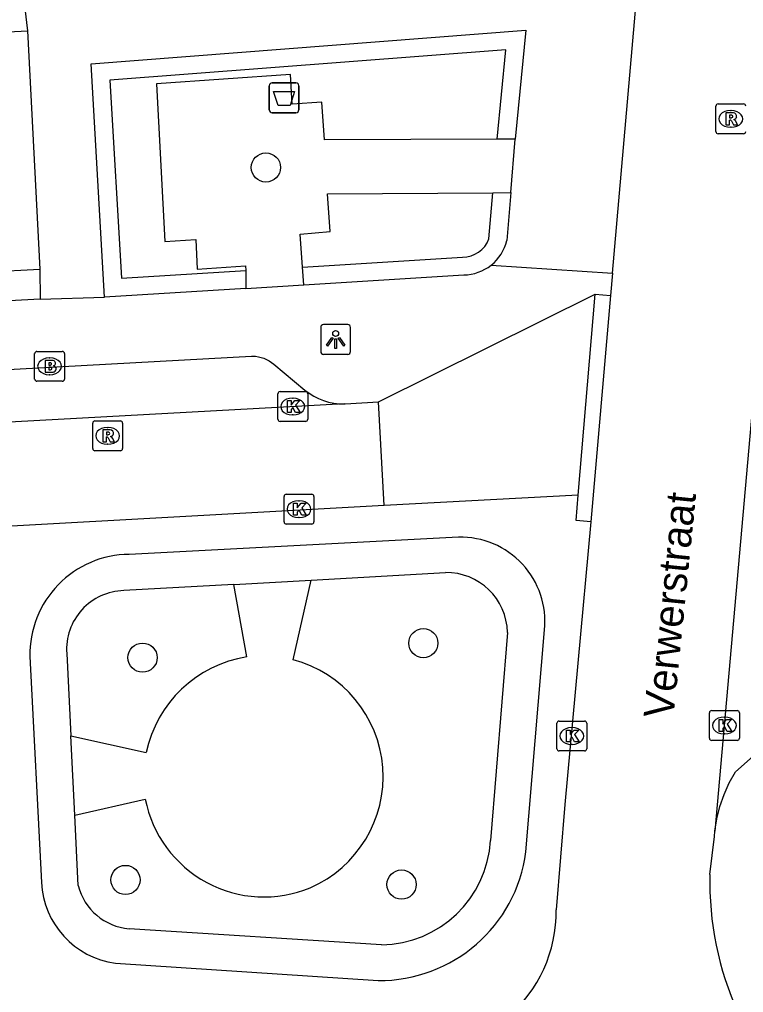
# Model space of a CAD drawing. Extents: x 160861 to 161308, y 384024 to 384878.
# Drawn here: x 161108.92 to 161133.18, y 384701.45 to 384734.04 of the extents above; entities that cross this region are included whole.
import ezdxf

# ---------------------------------------------------------------- set-up
doc = ezdxf.new("R2010")
doc.units = 0
for name, color, linetype in [('IMGEO_Afvalbak', 7, 'Continuous'), ('IMGEO_Boom', 7, 'Continuous'), ('IMGEO_Brandkraan', 7, 'Continuous'), ('IMGEO_Haag', 7, 'Continuous'), ('IMGEO_Kolk', 7, 'Continuous'), ('IMGEO_Lichtpunt', 7, 'Continuous'), ('IMGEO_Openbare_ruimte_label', 7, 'Continuous'), ('IMGEO_Pand', 7, 'Continuous'), ('IMGEO_Rijbaan_lokaal_open', 7, 'Continuous'), ('IMGEO_Rioolput', 7, 'Continuous'), ('IMGEO_Voetpad_open', 7, 'Continuous')]:
    doc.layers.add(name, color=color, linetype=linetype)

msp = doc.modelspace()

# ---------------------------------------------------------------- linework, layer by layer
at = {"layer": 'IMGEO_Afvalbak'}
for p, q in [((161117.289, 384731.014), (161117.289, 384731.814)), ((161117.289, 384731.814), (161117.289, 384731.014)), ((161117.389, 384731.914), (161118.179, 384731.914)), ((161118.179, 384731.914), (161117.389, 384731.914)), ((161118.279, 384731.814), (161118.279, 384731.014)), ((161118.279, 384731.014), (161118.279, 384731.814)), ((161118.179, 384730.914), (161117.389, 384730.914)), ((161117.389, 384730.914), (161118.179, 384730.914))]:
    msp.add_line(p, q, dxfattribs=at)
msp.add_lwpolyline([(161117.432, 384731.628), (161118.136, 384731.628), (161117.987, 384731.158), (161117.581, 384731.158), (161117.432, 384731.628)], dxfattribs=at)
for centre, start, end in [((161117.389, 384731.814), 90, 180), ((161117.389, 384731.814), 90, 180), ((161118.179, 384731.814), 0, 90), ((161118.179, 384731.814), 360, 90), ((161117.389, 384731.014), 180, 270), ((161117.389, 384731.014), 180, 270), ((161118.179, 384731.014), 270, 0), ((161118.179, 384731.014), 270, 0)]:
    msp.add_arc(centre, 0.1, start, end, dxfattribs=at)
at = {"layer": 'IMGEO_Boom'}
for centre in [(161117.175, 384729.078), (161122.448, 384713.149), (161113.042, 384712.663), (161112.47, 384705.218), (161121.719, 384705.064)]:
    msp.add_circle(centre, 0.489, dxfattribs=at)
at = {"layer": 'IMGEO_Brandkraan'}
for p, q in [((161109.427, 384721.993), (161109.427, 384722.845)), ((161109.502, 384722.919), (161110.354, 384722.919)), ((161110.428, 384722.845), (161110.428, 384721.993)), ((161109.915, 384722.699), (161109.94, 384722.699)), ((161110.354, 384721.919), (161109.502, 384721.919)), ((161109.938, 384722.139), (161109.913, 384722.139))]:
    msp.add_line(p, q, dxfattribs=at)
for points in [[(161109.427, 384721.993), (161109.427, 384722.845)], [(161109.502, 384722.919), (161110.354, 384722.919)], [(161110.428, 384722.845), (161110.428, 384721.993)], [(161109.775, 384722.619), (161109.775, 384722.219), (161109.988, 384722.219)], [(161110.006, 384722.619), (161109.775, 384722.619)], [(161109.954, 384722.538), (161109.9, 384722.538), (161109.9, 384722.462)], [(161109.9, 384722.462), (161109.953, 384722.462)], [(161109.962, 384722.386), (161109.9, 384722.386), (161109.9, 384722.305)], [(161109.9, 384722.305), (161109.962, 384722.305)], [(161110.354, 384721.919), (161109.502, 384721.919)]]:
    msp.add_lwpolyline(points, dxfattribs=at)
for centre, radius, start, end in [((161109.504, 384722.843), 0.0765, 91.552, 178.448), ((161109.504, 384722.843), 0.0765, 91.552, 178.448), ((161110.352, 384722.843), 0.0765, 1.552, 88.448), ((161110.352, 384722.843), 0.0765, 1.552, 88.448), ((161109.955, 384722.5), 0.0379, 267.8285, 90.9355), ((161110.01, 384722.474), 0.145, 59.4692, 91.5367), ((161110.035, 384722.521), 0.0922, 285.5137, 58.1501), ((161109.963, 384722.345), 0.0404, 269.8759, 90.5077), ((161109.994, 384722.47), 0.251, 268.6676, 293.5347), ((161110.04, 384722.329), 0.105, 301.3115, 78.989), ((161109.504, 384721.995), 0.0765, 181.552, 268.448), ((161109.504, 384721.995), 0.0765, 181.552, 268.448), ((161110.352, 384721.995), 0.0765, 271.552, 358.448), ((161110.352, 384721.995), 0.0765, 271.552, 358.448)]:
    msp.add_arc(centre, radius, start, end, dxfattribs=at)
for centre, major_axis, ratio, start_param, end_param in [((161109.914, 384722.419), (-0.387, 0.002), 0.722429, 4.712389, 7.853982), ((161109.939, 384722.419), (-0.39, 0.002), 0.717154, 1.570796, 4.712389)]:
    msp.add_ellipse(centre, major_axis=major_axis, ratio=ratio, start_param=start_param, end_param=end_param, dxfattribs=at)
at = {"layer": 'IMGEO_Haag'}
for points in [[(161124.926, 384730.028), (161125.216, 384733.021), (161111.949, 384732), (161112.335, 384725.367), (161116.498, 384725.626)], [(161124.646, 384726.684), (161124.777, 384728.232)], [(161118.403, 384725.745), (161123.764, 384726.079)]]:
    msp.add_lwpolyline(points, dxfattribs=at)
msp.add_arc((161123.771, 384727.014), 0.935, 269.5774, 339.3182, dxfattribs=at)
at = {"layer": 'IMGEO_Kolk'}
for p, q in [((161117.648, 384721.572), (161118.5, 384721.572)), ((161117.573, 384720.646), (161117.573, 384721.498)), ((161118.061, 384721.352), (161118.086, 384721.352)), ((161118.574, 384721.498), (161118.574, 384720.646)), ((161118.5, 384720.572), (161117.648, 384720.572)), ((161118.084, 384720.792), (161118.059, 384720.792)), ((161117.783, 384717.209), (161117.783, 384718.061)), ((161117.858, 384718.135), (161118.71, 384718.135)), ((161118.784, 384718.061), (161118.784, 384717.209)), ((161118.271, 384717.915), (161118.296, 384717.915)), ((161118.294, 384717.355), (161118.269, 384717.355)), ((161118.71, 384717.135), (161117.858, 384717.135)), ((161132.034, 384709.965), (161132.034, 384710.817)), ((161132.109, 384710.891), (161132.961, 384710.891)), ((161133.035, 384710.817), (161133.035, 384709.965)), ((161126.923, 384709.613), (161126.923, 384710.465)), ((161126.998, 384710.539), (161127.85, 384710.539)), ((161127.924, 384710.465), (161127.924, 384709.613)), ((161132.522, 384710.671), (161132.547, 384710.671)), ((161127.411, 384710.319), (161127.436, 384710.319)), ((161132.961, 384709.891), (161132.109, 384709.891)), ((161132.545, 384710.111), (161132.52, 384710.111)), ((161127.85, 384709.539), (161126.998, 384709.539)), ((161127.434, 384709.759), (161127.409, 384709.759))]:
    msp.add_line(p, q, dxfattribs=at)
for points in [[(161117.648, 384721.572), (161118.5, 384721.572)], [(161117.573, 384720.646), (161117.573, 384721.498)], [(161117.894, 384721.272), (161118.017, 384721.272), (161118.017, 384721.121), (161118.147, 384721.272), (161118.311, 384721.272), (161118.165, 384721.121), (161118.318, 384720.872), (161118.166, 384720.872), (161118.081, 384721.036), (161118.017, 384720.969), (161118.017, 384720.872), (161117.894, 384720.872), (161117.894, 384721.272)], [(161118.574, 384721.498), (161118.574, 384720.646)], [(161118.5, 384720.572), (161117.648, 384720.572)], [(161117.783, 384717.209), (161117.783, 384718.061)], [(161117.858, 384718.135), (161118.71, 384718.135)], [(161118.784, 384718.061), (161118.784, 384717.209)], [(161118.104, 384717.835), (161118.227, 384717.835), (161118.227, 384717.684), (161118.357, 384717.835), (161118.521, 384717.835), (161118.375, 384717.684), (161118.528, 384717.435), (161118.376, 384717.435), (161118.291, 384717.599), (161118.227, 384717.532), (161118.227, 384717.435), (161118.104, 384717.435), (161118.104, 384717.835)], [(161118.71, 384717.135), (161117.858, 384717.135)], [(161132.034, 384709.965), (161132.034, 384710.817)], [(161132.109, 384710.891), (161132.961, 384710.891)], [(161133.035, 384710.817), (161133.035, 384709.965)], [(161126.923, 384709.613), (161126.923, 384710.465)], [(161126.998, 384710.539), (161127.85, 384710.539)], [(161127.924, 384710.465), (161127.924, 384709.613)], [(161132.355, 384710.591), (161132.478, 384710.591), (161132.478, 384710.44), (161132.608, 384710.591), (161132.772, 384710.591), (161132.626, 384710.44), (161132.779, 384710.191), (161132.627, 384710.191), (161132.542, 384710.355), (161132.478, 384710.288), (161132.478, 384710.191), (161132.355, 384710.191), (161132.355, 384710.591)], [(161127.244, 384710.239), (161127.367, 384710.239), (161127.367, 384710.088), (161127.497, 384710.239), (161127.661, 384710.239), (161127.515, 384710.088), (161127.668, 384709.839), (161127.516, 384709.839), (161127.431, 384710.003), (161127.367, 384709.936), (161127.367, 384709.839), (161127.244, 384709.839), (161127.244, 384710.239)], [(161132.961, 384709.891), (161132.109, 384709.891)], [(161127.85, 384709.539), (161126.998, 384709.539)]]:
    msp.add_lwpolyline(points, dxfattribs=at)
for centre, start, end in [((161117.65, 384721.496), 91.552, 178.448), ((161117.65, 384721.496), 91.552, 178.448), ((161118.498, 384721.496), 1.552, 88.448), ((161118.498, 384721.496), 1.552, 88.448), ((161117.65, 384720.648), 181.552, 268.448), ((161117.65, 384720.648), 181.552, 268.448), ((161118.498, 384720.648), 271.552, 358.448), ((161118.498, 384720.648), 271.552, 358.448), ((161117.86, 384718.059), 91.552, 178.448), ((161117.86, 384718.059), 91.552, 178.448), ((161118.708, 384718.059), 1.552, 88.448), ((161118.708, 384718.059), 1.552, 88.448), ((161117.86, 384717.211), 181.552, 268.448), ((161117.86, 384717.211), 181.552, 268.448), ((161118.708, 384717.211), 271.552, 358.448), ((161118.708, 384717.211), 271.552, 358.448), ((161132.111, 384710.815), 91.552, 178.448), ((161132.111, 384710.815), 91.552, 178.448), ((161132.959, 384710.815), 1.552, 88.448), ((161132.959, 384710.815), 1.552, 88.448), ((161127, 384710.463), 91.552, 178.448), ((161127, 384710.463), 91.552, 178.448), ((161127.848, 384710.463), 1.552, 88.448), ((161127.848, 384710.463), 1.552, 88.448), ((161132.111, 384709.967), 181.552, 268.448), ((161132.111, 384709.967), 181.552, 268.448), ((161132.959, 384709.967), 271.552, 358.448), ((161132.959, 384709.967), 271.552, 358.448), ((161127, 384709.615), 181.552, 268.448), ((161127, 384709.615), 181.552, 268.448), ((161127.848, 384709.615), 271.552, 358.448), ((161127.848, 384709.615), 271.552, 358.448)]:
    msp.add_arc(centre, 0.0765, start, end, dxfattribs=at)
for centre, major_axis, ratio, start_param, end_param in [((161118.06, 384721.072), (-0.387, 0.002), 0.722429, 4.712389, 7.853982), ((161118.085, 384721.072), (-0.39, 0.002), 0.717154, 1.570796, 4.712389), ((161118.27, 384717.635), (-0.387, 0.002), 0.722429, 4.712389, 7.853982), ((161118.295, 384717.635), (-0.39, 0.002), 0.717154, 1.570796, 4.712389), ((161132.521, 384710.391), (-0.387, 0.002), 0.722429, 4.712389, 7.853982), ((161132.546, 384710.391), (-0.39, 0.002), 0.717154, 1.570796, 4.712389), ((161127.41, 384710.039), (-0.387, 0.002), 0.722429, 4.712389, 7.853982), ((161127.435, 384710.039), (-0.39, 0.002), 0.717154, 1.570796, 4.712389)]:
    msp.add_ellipse(centre, major_axis=major_axis, ratio=ratio, start_param=start_param, end_param=end_param, dxfattribs=at)
at = {"layer": 'IMGEO_Lichtpunt'}
for p, q in [((161119.012, 384723.722), (161119.012, 384722.915)), ((161119.012, 384723.722), (161119.012, 384722.915)), ((161119.914, 384723.817), (161119.106, 384723.817)), ((161119.914, 384723.817), (161119.106, 384723.817)), ((161120.008, 384722.915), (161120.008, 384723.722)), ((161120.008, 384722.915), (161120.008, 384723.722)), ((161119.106, 384722.821), (161119.914, 384722.821)), ((161119.106, 384722.821), (161119.914, 384722.821))]:
    msp.add_line(p, q, dxfattribs=at)
for points in [[(161119.386, 384723.386), (161119.425, 384723.358), (161119.237, 384723.096), (161119.199, 384723.123), (161119.386, 384723.386)], [(161119.488, 384723.338), (161119.535, 384723.338), (161119.535, 384723.016), (161119.488, 384723.016), (161119.488, 384723.338)], [(161119.598, 384723.358), (161119.636, 384723.385), (161119.823, 384723.123), (161119.784, 384723.095), (161119.598, 384723.358)]]:
    msp.add_lwpolyline(points, dxfattribs=at)
msp.add_circle((161119.511, 384723.52), 0.0994, dxfattribs=at)
for centre, start, end in [((161119.106, 384723.722), 90, 180), ((161119.106, 384723.722), 90, 180), ((161119.914, 384723.722), 0, 90), ((161119.914, 384723.722), 0, 90), ((161119.106, 384722.915), 180, 270), ((161119.106, 384722.915), 180, 270), ((161119.914, 384722.915), 270, 0), ((161119.914, 384722.915), 270, 360)]:
    msp.add_arc(centre, 0.0946, start, end, dxfattribs=at)
at = {"layer": 'IMGEO_Pand'}
for points in [[(161104.049, 384733.386), (161104.193, 384733.394), (161109.186, 384733.651)], [(161109.186, 384733.651), (161109.597, 384725.668)], [(161104.46, 384725.404), (161109.597, 384725.668)]]:
    msp.add_lwpolyline(points, dxfattribs=at)
at = {"layer": 'IMGEO_Rijbaan_lokaal_open'}
for points in [[(161134.909, 384737.229), (161132.216, 384706.852)], [(161128.787, 384725.541), (161129.676, 384735.749)], [(161128.787, 384725.541), (161128.722, 384724.796)], [(161120.943, 384721.23), (161128.202, 384724.839)], [(161127.641, 384718.106), (161128.202, 384724.839)], [(161128.722, 384724.796), (161128.062, 384717.217)], [(161119.802, 384721.162), (161119.828, 384721.163), (161120.943, 384721.23)], [(161121.139, 384717.759), (161120.943, 384721.23)], [(161119.802, 384721.162), (161071.831, 384718.54)], [(161127.641, 384718.106), (161121.139, 384717.759)], [(161121.139, 384717.759), (161108.035, 384717.035)], [(161128.062, 384717.217), (161127.187, 384707.75), (161126.904, 384704.217)], [(161132.051, 384705.402), (161132.2, 384706.676), (161132.216, 384706.852)]]:
    msp.add_lwpolyline(points, dxfattribs=at)
for centre, radius, start, end in [((161142.457, 384705.114), 10.41, 178.4162, 204.6414), ((161122.242, 384704.17), 4.662, 310.3401, 0.5827)]:
    msp.add_arc(centre, radius, start, end, dxfattribs=at)
at = {"layer": 'IMGEO_Rioolput'}
for p, q in [((161132.249, 384730.28), (161132.249, 384731.132)), ((161132.324, 384731.206), (161133.176, 384731.206)), ((161132.737, 384730.986), (161132.762, 384730.986)), ((161132.76, 384730.426), (161132.735, 384730.426)), ((161133.176, 384730.206), (161132.324, 384730.206)), ((161111.446, 384720.592), (161112.298, 384720.592)), ((161111.371, 384719.666), (161111.371, 384720.518)), ((161111.859, 384720.372), (161111.884, 384720.372)), ((161112.372, 384720.518), (161112.372, 384719.666)), ((161112.298, 384719.592), (161111.446, 384719.592)), ((161111.882, 384719.812), (161111.857, 384719.812))]:
    msp.add_line(p, q, dxfattribs=at)
for points in [[(161132.249, 384730.28), (161132.249, 384731.132)], [(161132.324, 384731.206), (161133.176, 384731.206)], [(161132.838, 384730.904), (161132.586, 384730.906), (161132.586, 384730.506)], [(161132.586, 384730.506), (161132.71, 384730.506), (161132.71, 384730.668), (161132.721, 384730.668)], [(161132.764, 384730.825), (161132.71, 384730.825), (161132.71, 384730.744)], [(161132.71, 384730.744), (161132.762, 384730.744)], [(161132.768, 384730.639), (161132.839, 384730.506), (161132.979, 384730.506), (161132.914, 384730.632)], [(161133.176, 384730.206), (161132.324, 384730.206)], [(161111.446, 384720.592), (161112.298, 384720.592)], [(161111.371, 384719.666), (161111.371, 384720.518)], [(161111.96, 384720.29), (161111.708, 384720.292), (161111.708, 384719.892)], [(161112.372, 384720.518), (161112.372, 384719.666)], [(161111.708, 384719.892), (161111.832, 384719.892), (161111.832, 384720.054), (161111.843, 384720.054)], [(161111.886, 384720.211), (161111.832, 384720.211), (161111.832, 384720.13)], [(161111.832, 384720.13), (161111.884, 384720.13)], [(161111.89, 384720.025), (161111.961, 384719.892), (161112.101, 384719.892), (161112.036, 384720.018)], [(161112.298, 384719.592), (161111.446, 384719.592)]]:
    msp.add_lwpolyline(points, dxfattribs=at)
for centre, radius, start, end in [((161132.326, 384731.13), 0.0765, 91.552, 178.448), ((161132.326, 384731.13), 0.0765, 91.552, 178.448), ((161133.174, 384731.13), 0.0765, 1.552, 88.448), ((161133.174, 384731.13), 0.0765, 1.552, 88.448), ((161132.72, 384730.615), 0.0533, 26.0293, 88.6989), ((161132.746, 384730.933), 0.19, 274.7715, 282.9687), ((161132.77, 384730.729), 0.0964, 77.0061, 93.1865), ((161132.784, 384730.786), 0.0378, 276.6634, 79.6772), ((161132.837, 384730.794), 0.109, 350.3612, 89.416), ((161132.835, 384730.794), 0.112, 277.5842, 350.9817), ((161132.819, 384730.579), 0.108, 29.5134, 73.7905), ((161132.326, 384730.282), 0.0765, 181.552, 268.448), ((161132.326, 384730.282), 0.0765, 181.552, 268.448), ((161133.174, 384730.282), 0.0765, 271.552, 358.448), ((161133.174, 384730.282), 0.0765, 271.552, 358.448), ((161111.448, 384720.516), 0.0765, 91.552, 178.448), ((161111.448, 384720.516), 0.0765, 91.552, 178.448), ((161112.296, 384720.516), 0.0765, 1.552, 88.448), ((161112.296, 384720.516), 0.0765, 1.552, 88.448), ((161111.959, 384720.18), 0.109, 350.3612, 89.416), ((161111.842, 384720.001), 0.0533, 26.0293, 88.6989), ((161111.868, 384720.319), 0.19, 274.7715, 282.9687), ((161111.892, 384720.115), 0.0964, 77.0061, 93.1865), ((161111.906, 384720.172), 0.0378, 276.6634, 79.6772), ((161111.957, 384720.18), 0.112, 277.5842, 350.9817), ((161111.941, 384719.965), 0.108, 29.5134, 73.7905), ((161111.448, 384719.668), 0.0765, 181.552, 268.448), ((161111.448, 384719.668), 0.0765, 181.552, 268.448), ((161112.296, 384719.668), 0.0765, 271.552, 358.448), ((161112.296, 384719.668), 0.0765, 271.552, 358.448)]:
    msp.add_arc(centre, radius, start, end, dxfattribs=at)
for centre, major_axis, ratio, start_param, end_param in [((161132.736, 384730.706), (-0.387, 0.002), 0.722429, 4.712389, 7.853982), ((161132.761, 384730.706), (-0.39, 0.002), 0.717154, 1.570796, 4.712389), ((161111.858, 384720.092), (-0.387, 0.002), 0.722429, 4.712389, 7.853982), ((161111.883, 384720.092), (-0.39, 0.002), 0.717154, 1.570796, 4.712389)]:
    msp.add_ellipse(centre, major_axis=major_axis, ratio=ratio, start_param=start_param, end_param=end_param, dxfattribs=at)
at = {"layer": 'IMGEO_Voetpad_open'}
for points in [[(161109.099, 384734.403), (161109.186, 384733.651)], [(161111.771, 384724.731), (161111.316, 384732.553), (161125.882, 384733.674), (161125.529, 384730.031)], [(161124.926, 384730.028), (161119.139, 384730), (161119.044, 384731.264), (161118.057, 384731.201), (161118, 384732.196), (161113.506, 384731.882), (161113.792, 384726.598), (161114.825, 384726.663), (161114.875, 384725.669), (161116.496, 384725.789), (161116.498, 384725.626)], [(161125.529, 384730.031), (161124.926, 384730.028)], [(161125.379, 384728.236), (161125.529, 384730.031)], [(161118.403, 384725.745), (161118.319, 384726.849), (161119.325, 384726.929), (161119.241, 384728.195), (161124.777, 384728.232)], [(161124.777, 384728.232), (161125.379, 384728.236)], [(161125.379, 384728.236), (161125.244, 384726.633)], [(161124.721, 384725.808), (161128.787, 384725.541)], [(161109.597, 384725.668), (161109.616, 384724.666)], [(161116.498, 384725.626), (161116.502, 384725.026)], [(161118.448, 384725.147), (161118.403, 384725.745)], [(161118.448, 384725.147), (161123.801, 384725.48)], [(161116.502, 384725.026), (161118.448, 384725.147)], [(161116.502, 384725.026), (161111.771, 384724.731)], [(161128.202, 384724.839), (161128.722, 384724.796)], [(161109.616, 384724.666), (161069.34, 384722.503)], [(161109.616, 384724.666), (161111.771, 384724.731)], [(161074.676, 384720.464), (161116.687, 384722.757), (161116.731, 384722.758), (161116.827, 384722.754), (161116.923, 384722.741), (161117.017, 384722.719), (161117.109, 384722.689), (161117.198, 384722.652), (161117.283, 384722.606), (161117.363, 384722.553), (161117.439, 384722.493), (161118.481, 384721.623), (161118.623, 384721.515), (161118.775, 384721.42), (161118.934, 384721.339), (161119.1, 384721.273), (161119.271, 384721.222), (161119.446, 384721.186), (161119.624, 384721.166), (161119.802, 384721.162)], [(161128.062, 384717.217), (161127.57, 384717.257), (161127.641, 384718.106)], [(161123.627, 384716.695), (161112.597, 384716.123)], [(161118.692, 384715.261), (161123.187, 384715.514)], [(161116.099, 384715.115), (161112.417, 384714.908)], [(161116.099, 384715.115), (161118.692, 384715.261)], [(161116.535, 384712.688), (161116.099, 384715.115)], [(161118.086, 384712.593), (161118.692, 384715.261)], [(161125.268, 384713.509), (161124.703, 384706.539)], [(161125.887, 384706.156), (161126.511, 384713.592)], [(161110.501, 384712.803), (161110.639, 384710.042)], [(161109.269, 384712.701), (161109.658, 384705.131)], [(161110.772, 384707.385), (161110.639, 384710.042)], [(161110.639, 384710.042), (161113.163, 384709.483)], [(161132.216, 384706.852), (161132.281, 384707.27), (161132.384, 384707.682), (161132.523, 384708.084), (161132.697, 384708.472), (161132.905, 384708.842), (161133.8, 384709.628)], [(161110.772, 384707.385), (161113.13, 384707.929)], [(161110.89, 384705.03), (161110.772, 384707.385)], [(161121.045, 384703.042), (161112.591, 384703.586)], [(161112.133, 384702.431), (161120.933, 384701.85)]]:
    msp.add_lwpolyline(points, dxfattribs=at)
for centre, radius, start, end in [((161123.789, 384726.977), 1.496, 308.5687, 346.6868), ((161123.784, 384726.982), 1.502, 270.6515, 308.593), ((161123.699, 384713.871), 2.825, 354.3405, 91.4697), ((161112.625, 384712.766), 3.357, 90.4788, 181.1169), ((161123.213, 384713.458), 2.056, 1.4122, 90.719), ((161112.462, 384712.943), 1.966, 91.3008, 184.0814), ((161117.174, 384708.639), 4.099, 98.9698, 168.1212), ((161117.049, 384708.676), 4.052, 293.4078, 75.175), ((161117.112, 384708.708), 4.057, 191.067, 292.4143), ((161120.977, 384706.774), 3.733, 271.0361, 356.3858), ((161120.974, 384706.805), 4.955, 269.5215, 352.4727), ((161112.516, 384705.267), 2.861, 182.7172, 262.3037), ((161112.74, 384705.486), 1.905, 193.8326, 265.5107)]:
    msp.add_arc(centre, radius, start, end, dxfattribs=at)

# ---------------------------------------------------------------- texts
at = {"layer": 'IMGEO_Openbare_ruimte_label'}
msp.add_text('Verwerstraat', height=1, rotation=84.2039, dxfattribs=at).set_placement((161130.821, 384710.601))

doc.saveas('drawing.dxf')
